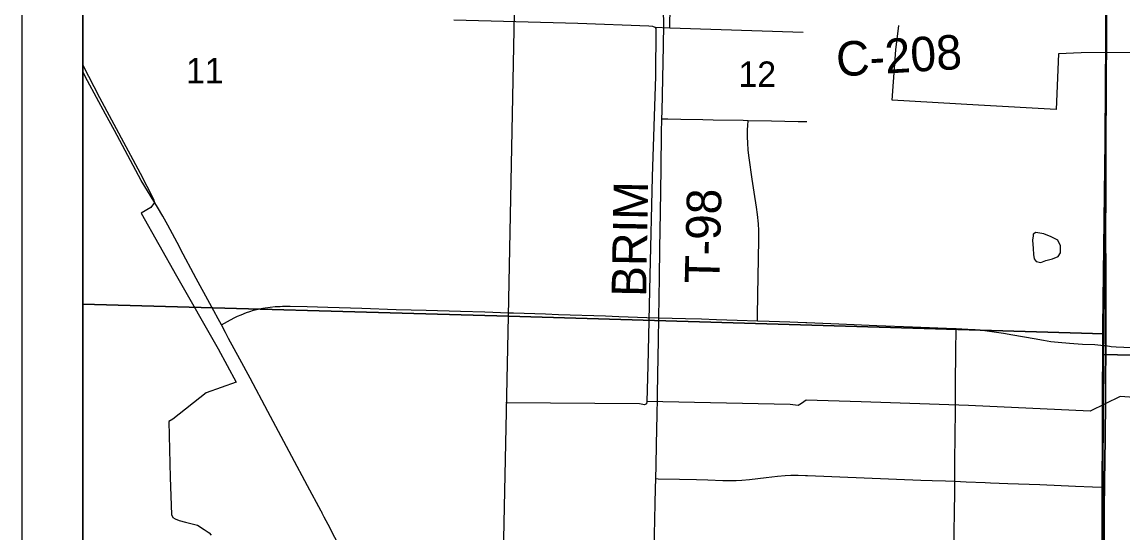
# Model space of a CAD drawing. Extents: x -59 to 43, y 0 to 22.
# Drawn here: x 23.417 to 25.228, y 18.99 to 19.831 of the extents above; entities that cross this region are included whole.
import ezdxf

# ---------------------------------------------------------------- set-up
doc = ezdxf.new("R2010")
doc.units = 0
for name, color, linetype in [('Default', 7, 'Continuous'), ('GM_X_City_Street', 7, 'Continuous'), ('GM_X_County_Road_Text', 7, 'Continuous'), ('GM_X_Interchange_Ramps', 7, 'Continuous'), ('GM_X_Major_River', 7, 'Continuous'), ('GM_X_Minor_Lake', 7, 'Continuous'), ('GM_X_Minor_River', 7, 'Continuous'), ('GM_X_Rail_Line', 7, 'Continuous'), ('GM_X_Section', 7, 'Continuous'), ('GM_X_Section_Text', 7, 'Continuous'), ('GM_X_State_Route', 7, 'Continuous'), ('GM_X_Township_Road', 7, 'Continuous'), ('GM_X_Township_Road_Text', 7, 'Continuous'), ('SH_Data', 7, 'Continuous')]:
    doc.layers.add(name, color=color, linetype=linetype)

msp = doc.modelspace()

# ---------------------------------------------------------------- linework, layer by layer
at = {"layer": 'Default'}
for points in [[(23.5167, 20.3678), (23.5167, 19.3671), (24.217, 19.3472), (24.2369, 20.3455)], [(23.5167, 19.3671), (23.5167, 18.3646), (24.1964, 18.3523), (24.217, 19.3472)]]:
    msp.add_lwpolyline(points, close=True, dxfattribs=at)
at = {"layer": 'GM_X_City_Street'}
for points in [[(24.4694, 19.6719), (24.4791, 19.6717), (24.5008, 19.6714), (24.5365, 19.6706), (24.5535, 19.6702), (24.6032, 19.6695), (24.6112, 19.6694), (24.6497, 19.6687), (24.6936, 19.6675), (24.7076, 19.6675)], [(24.6265, 19.3394), (24.6266, 19.347), (24.6272, 19.3827), (24.628, 19.4121), (24.6289, 19.4726), (24.6287, 19.4881), (24.6282, 19.4989), (24.6267, 19.5143), (24.6251, 19.5265), (24.6213, 19.5511), (24.618, 19.5725), (24.6129, 19.6079), (24.6116, 19.6202), (24.6106, 19.6326), (24.6103, 19.642), (24.6104, 19.6544), (24.6108, 19.6607), (24.6112, 19.6694)], [(23.7446, 19.3328), (23.7548, 19.3384), (23.7658, 19.3443), (23.7714, 19.3471), (23.7771, 19.3496), (23.7858, 19.353), (23.7917, 19.355), (23.7977, 19.3568), (23.813, 19.3602), (23.8247, 19.362), (23.8332, 19.3628), (23.8415, 19.3633), (23.8452, 19.3635), (23.8577, 19.3635), (23.8857, 19.3628), (23.9199, 19.3618), (23.976, 19.3601), (24.032, 19.3583), (24.0818, 19.3568), (24.1378, 19.3553), (24.1783, 19.3542), (24.2173, 19.3529), (24.225, 19.3527), (24.2779, 19.3509), (24.2992, 19.3501), (24.3765, 19.3477), (24.3985, 19.3467), (24.4444, 19.345), (24.4645, 19.3443), (24.5082, 19.3433), (24.5345, 19.3426), (24.5593, 19.3418), (24.5934, 19.3406), (24.6265, 19.3394), (24.6461, 19.3388), (24.6801, 19.3378), (24.7062, 19.3368), (24.708, 19.3367), (24.7606, 19.3346), (24.8228, 19.332), (24.8819, 19.3296), (24.9379, 19.3273), (24.9537, 19.3266), (24.9725, 19.3259), (24.9849, 19.325), (25.0005, 19.3236), (25.016, 19.3216), (25.0315, 19.3193), (25.0469, 19.3166), (25.082, 19.3102), (25.0972, 19.3074), (25.1093, 19.3056), (25.1215, 19.3041), (25.1399, 19.3026), (25.1615, 19.3012), (25.1818, 19.3005), (25.1914, 19.2997), (25.1976, 19.2991), (25.2, 19.2988)], [(24.9514, 19.0754), (24.9515, 19.0876), (24.9515, 19.1061), (24.9521, 19.1525), (24.9522, 19.1897), (24.9527, 19.2361), (24.9532, 19.2887), (24.9537, 19.3266)]]:
    msp.add_lwpolyline(points, dxfattribs=at)
at = {"layer": 'GM_X_Interchange_Ramps'}
for points in [[(23.5167, 20.9), (23.5167, 15.3531)], [(25.2009, 19.87), (25.2006, 19.8022), (25.2006, 19.79), (25.2004, 19.7478), (25.2004, 19.7398), (25.2003, 19.7122), (25.2001, 19.6898), (25.1999, 19.6639), (25.1997, 19.6241), (25.1997, 19.6188), (25.1997, 19.6048), (25.1997, 19.583), (25.1996, 19.5418), (25.1994, 19.4921), (25.2, 19.4097), (25.2, 19.4066), (25.1999, 19.3527), (25.1998, 19.3329), (25.1998, 19.3064), (25.1998, 19.2994), (25.1997, 19.2801), (25.1994, 19.2505), (25.199, 19.2101), (25.1987, 19.1447), (25.1976, 19.0751), (25.1975, 19.0665), (25.1972, 19.0354), (25.1968, 18.9998), (25.1963, 18.9392)], [(25.1963, 18.9392), (25.1968, 18.9998), (25.1972, 19.0354), (25.1975, 19.0665), (25.1976, 19.0751), (25.1987, 19.1447), (25.199, 19.2101), (25.1994, 19.2505), (25.1997, 19.2801), (25.1998, 19.2994), (25.1998, 19.3064), (25.1998, 19.3329), (25.1999, 19.3527), (25.2, 19.4066), (25.2, 19.4097), (25.1994, 19.4921), (25.1996, 19.5418), (25.1997, 19.583), (25.1997, 19.6048), (25.1997, 19.6188), (25.1997, 19.6241), (25.1999, 19.6639), (25.2001, 19.6898), (25.2003, 19.7122), (25.2004, 19.7398), (25.2004, 19.7478), (25.2006, 19.79), (25.2006, 19.8022), (25.2009, 19.87)]]:
    msp.add_lwpolyline(points, dxfattribs=at)
at = {"layer": 'GM_X_Major_River'}
msp.add_lwpolyline([(25.5124, 19.1944), (25.2233, 19.215), (25.1739, 19.1909), (24.9738, 19.2), (24.7971, 19.2063), (24.7069, 19.2091), (24.6992, 19.2036), (24.6938, 19.2003), (24.6806, 19.2016), (24.4447, 19.2065)], dxfattribs=at)
at = {"layer": 'GM_X_Minor_Lake'}
msp.add_line((25.0791, 19.4724), (25.08, 19.4583), dxfattribs=at)
msp.add_lwpolyline([(25.08, 19.4583), (25.0806, 19.4484), (25.0819, 19.4416), (25.0849, 19.4373), (25.0928, 19.4357), (25.1009, 19.4389), (25.1123, 19.4418), (25.1215, 19.4454), (25.125, 19.4514), (25.1252, 19.4632), (25.1208, 19.4724), (25.1096, 19.4779), (25.0975, 19.4827), (25.0847, 19.4848), (25.0801, 19.4819), (25.08, 19.4792), (25.0791, 19.4724)], dxfattribs=at)
at = {"layer": 'GM_X_Minor_River'}
for points in [[(24.4825, 19.8219), (24.4865, 20.0715), (24.4888, 20.2125), (24.4912, 20.3341), (24.4942, 20.5747)], [(24.1273, 19.835), (24.3313, 19.8293), (24.4481, 19.8252), (24.4538, 19.8247), (24.4579, 19.8231), (24.4594, 19.8204), (24.4587, 19.7421), (24.4536, 19.5765), (24.4494, 19.4143), (24.4465, 19.2653), (24.4447, 19.2065), (24.4442, 19.203), (24.4408, 19.2012), (24.4325, 19.2029), (24.2128, 19.2044)], [(24.4579, 19.8231), (24.4825, 19.8219), (24.7017, 19.8144)], [(26.2319, 19.7602), (25.9873, 19.7663), (25.847, 19.7701), (25.693, 19.7733), (25.5436, 19.7765), (25.3866, 19.7795), (25.2587, 19.7811), (25.1593, 19.7807), (25.1221, 19.7791), (25.1181, 19.6872), (24.9904, 19.6945), (24.8483, 19.7025), (24.8544, 19.7853), (24.8593, 19.8255)], [(23.5167, 19.7604), (23.5441, 19.7073), (23.6111, 19.5825), (23.6331, 19.5399), (23.6349, 19.5342), (23.6286, 19.5259), (23.6125, 19.5167), (23.6709, 19.4137), (23.7395, 19.2935), (23.7692, 19.2386), (23.7196, 19.2212), (23.6649, 19.1774), (23.658, 19.1738), (23.6604, 19.0817), (23.6627, 19.0205), (23.6648, 19.0159), (23.6686, 19.0135), (23.6754, 19.0107), (23.6859, 19.0083), (23.7052, 19.003), (23.7161, 18.9963), (23.7243, 18.9908), (23.728, 18.9866)]]:
    msp.add_lwpolyline(points, dxfattribs=at)
at = {"layer": 'GM_X_Rail_Line'}
msp.add_lwpolyline([(25.1883, 17.5646), (25.1947, 19.3296), (25.2084, 20.4232), (25.2113, 20.9)], dxfattribs=at)
at = {"layer": 'GM_X_Section'}
for points in [[(24.2369, 20.3455), (25.2037, 20.3168), (25.2029, 20.288), (25.1966, 19.318), (24.217, 19.3472)], [(26.3156, 20.2658), (26.283, 19.2582), (25.1962, 19.2843), (25.1966, 19.318), (25.2029, 20.288)], [(24.217, 19.3472), (25.1966, 19.318), (25.1962, 19.2843), (25.1906, 18.3142), (24.1964, 18.3523)], [(25.1962, 19.2843), (26.283, 19.2582), (26.2571, 18.8106), (26.2659, 18.2705), (25.1911, 18.2964), (25.1906, 18.3142)]]:
    msp.add_lwpolyline(points, close=True, dxfattribs=at)
at = {"layer": 'GM_X_State_Route'}
for p, q in [((25.2008, 19.7895), (25.2008, 19.7966)), ((25.2006, 19.7117), (25.2006, 19.7392)), ((25.2, 19.6236), (25.2, 19.6266))]:
    msp.add_line(p, q, dxfattribs=at)
for points in [[(25.2008, 19.7966), (25.2008, 19.8016), (25.2012, 19.8695)], [(25.2006, 19.7392), (25.2006, 19.7472), (25.2008, 19.7895)], [(23.6775, 19.4577), (23.6756, 19.4612), (23.6566, 19.4969), (23.6482, 19.5118), (23.6394, 19.5265), (23.6129, 19.5703), (23.6041, 19.5867), (23.5689, 19.6525), (23.554, 19.6798), (23.5246, 19.7346), (23.5167, 19.7493)], [(25.2, 19.6266), (25.2002, 19.6633), (25.2003, 19.6893), (25.2006, 19.7117)], [(25.1999, 19.5825), (25.2, 19.6042), (25.1999, 19.6182), (25.2, 19.6236)], [(25.2001, 19.3532), (25.2002, 19.4061), (25.2003, 19.4092), (25.1996, 19.4915), (25.1998, 19.5412), (25.1999, 19.5825)], [(23.7256, 19.3682), (23.7034, 19.4092), (23.6775, 19.4577)], [(23.7446, 19.3328), (23.7391, 19.343), (23.7322, 19.356), (23.7256, 19.3682)], [(25.1992, 19.2036), (25.1993, 19.2095), (25.1997, 19.2499), (25.1999, 19.2795), (25.2, 19.2988), (25.2001, 19.3059), (25.2, 19.3323), (25.2001, 19.3522), (25.2001, 19.3532)], [(23.9092, 19.0254), (23.9087, 19.0261), (23.8862, 19.0681), (23.8606, 19.1161), (23.8344, 19.1654), (23.8212, 19.1901), (23.7919, 19.2449), (23.775, 19.2763), (23.7566, 19.3105), (23.7515, 19.3201), (23.7446, 19.3328)], [(25.1987, 19.127), (25.199, 19.1442), (25.1992, 19.2036)], [(25.1964, 18.9138), (25.1965, 18.9386), (25.197, 18.9992), (25.1974, 19.0348), (25.1977, 19.0659), (25.1979, 19.0745), (25.1987, 19.127)], [(23.914, 19.0161), (23.9104, 19.023), (23.9092, 19.0254)], [(23.9365, 18.9736), (23.9315, 18.9831), (23.9202, 19.0044), (23.914, 19.0161)]]:
    msp.add_lwpolyline(points, dxfattribs=at)
at = {"layer": 'GM_X_Township_Road'}
for points in [[(24.4694, 19.6719), (24.4696, 19.6848), (24.472, 19.792), (24.4727, 19.8277), (24.4726, 19.8366), (24.4723, 19.8417), (24.4718, 19.846)], [(24.4645, 19.3443), (24.4648, 19.3772), (24.4654, 19.4114), (24.466, 19.458), (24.4666, 19.4891), (24.4671, 19.517), (24.4682, 19.59), (24.469, 19.6491), (24.4694, 19.6719)], [(24.4594, 19.0797), (24.46, 19.1016), (24.4607, 19.1358), (24.4615, 19.1854), (24.4619, 19.2117), (24.462, 19.218), (24.4625, 19.2506), (24.4638, 19.308), (24.4645, 19.3443)], [(25.2, 19.2988), (25.2088, 19.2974), (25.217, 19.2966), (25.2541, 19.2949), (25.2691, 19.2939), (25.2839, 19.293), (25.2925, 19.2921), (25.3014, 19.2911), (25.3447, 19.2865), (25.3571, 19.2855), (25.3695, 19.2849), (25.4099, 19.2837), (25.4689, 19.2817), (25.5417, 19.2793)], [(24.4568, 18.9677), (24.4572, 18.9876), (24.4578, 19.0117), (24.4584, 19.0396), (24.459, 19.0629), (24.4594, 19.0797)], [(24.4594, 19.0797), (24.463, 19.0796), (24.4983, 19.0788), (24.5261, 19.0781), (24.545, 19.0776), (24.5699, 19.0767), (24.5823, 19.0765), (24.5875, 19.0767)], [(24.5875, 19.0767), (24.5917, 19.0768), (24.601, 19.0774), (24.6134, 19.0785), (24.6412, 19.0818), (24.6597, 19.0838), (24.6721, 19.0848), (24.6813, 19.0852), (24.6937, 19.0854), (24.7054, 19.0851)], [(24.7054, 19.0851), (24.7092, 19.0851), (24.8955, 19.0773), (24.9141, 19.0768), (24.9359, 19.0761), (24.9514, 19.0754)], [(24.9473, 18.5649), (24.9474, 18.5669), (24.948, 18.6228), (24.948, 18.657), (24.9487, 18.7037), (24.9487, 18.7161), (24.9492, 18.7534), (24.9495, 18.7876), (24.9494, 18.8373), (24.9495, 18.8808), (24.9497, 18.9213), (24.9497, 18.9399), (24.9505, 18.9897), (24.9508, 19.027), (24.9513, 19.0549), (24.9514, 19.0754)], [(24.9514, 19.0754), (24.97, 19.0745), (25.001, 19.0734), (25.0101, 19.073)], [(25.0101, 19.073), (25.0383, 19.0719), (25.0911, 19.0699), (25.15, 19.0674), (25.178, 19.0662), (25.1977, 19.0659)]]:
    msp.add_lwpolyline(points, dxfattribs=at)
at = {"layer": 'SH_Data'}
for points in [[(23.4167, 21), (30.4167, 21), (30.4167, 14), (23.4167, 14)], [(23.5167, 20.9), (30.3167, 20.9), (30.3167, 14.1), (23.5167, 14.1)]]:
    msp.add_lwpolyline(points, close=True, dxfattribs=at)

# ---------------------------------------------------------------- texts
at = {"layer": 'GM_X_County_Road_Text'}
msp.add_text('C-208', height=0.05682, rotation=3.5751, dxfattribs=at).set_placement((24.7578, 19.7414))
at = {"layer": 'GM_X_Section_Text'}
for s, p in [('11', (23.6863, 19.7304)), ('12', (24.5951, 19.7245))]:
    msp.add_text(s, height=0.04186, rotation=0, dxfattribs=at).set_placement(p)
at = {"layer": 'GM_X_Township_Road_Text'}
for s, rotation, p in [('BRIM', 88.9352, (24.4434, 19.3786)), ('T-98', 88.6067, (24.5637, 19.4002))]:
    msp.add_text(s, height=0.05682, rotation=rotation, dxfattribs=at).set_placement(p)

doc.saveas('drawing.dxf')
